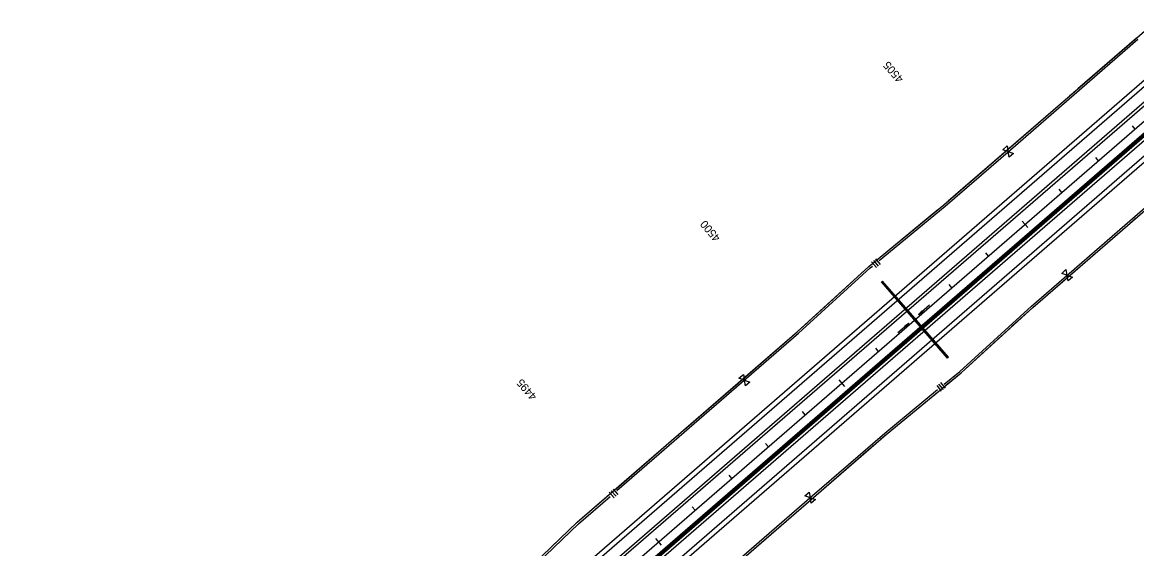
# Model space of a CAD drawing. Extents: x 192699 to 285914, y 194342 to 233219.
# Drawn here: x 198915 to 201213, y 200182 to 201267 of the extents above; entities that cross this region are included whole.
import ezdxf

# ---------------------------------------------------------------- set-up
doc = ezdxf.new("R2010")
doc.units = 0
for name, color, linetype in [('CENT LINE', 7, 'Continuous'), ('CONCRETE', 7, 'Continuous'), ('DRAINAGE', 7, 'Continuous'), ('DRAINAGE ARROWS', 7, 'Continuous'), ('R-W - CofA', 7, 'Continuous'), ('R_Water Annot', 7, 'Continuous'), ('ROAD', 7, 'Continuous'), ('SHOULDER', 7, 'Continuous'), ('STATIONING1', 7, 'Continuous'), ('WRSF', 7, 'Continuous')]:
    doc.layers.add(name, color=color, linetype=linetype)

msp = doc.modelspace()

# ---------------------------------------------------------------- linework, layer by layer
at = {"layer": 'CENT LINE'}
msp.add_line((198833.2, 198989.9), (207514.6, 206505.5), dxfattribs=at)
at = {"layer": 'CONCRETE'}
for p, q in [((198845, 198976.3), (202641.5, 202263)), ((198847.6, 198973.2), (202644.1, 202259.9))]:
    msp.add_line(p, q, dxfattribs=at)
at = {"layer": 'DRAINAGE'}
for p, q in [((200753.5, 200655.2), (200686.8, 200732.2)), ((200755.7, 200657.2), (200689.1, 200734.1)), ((200823, 200574.9), (200756.4, 200651.9)), ((200825.2, 200576.9), (200758.6, 200653.8))]:
    msp.add_line(p, q, dxfattribs=at)
for points in [[(200686.8, 200732.2), (200689.1, 200734.1)], [(200823, 200574.9), (200825.2, 200576.9)]]:
    msp.add_lwpolyline(points, dxfattribs=at)
msp.add_lwpolyline([(200755.8, 200651.4), (200759.1, 200654.3), (200756.3, 200657.6), (200752.9, 200654.7)], close=True, dxfattribs=at)
at = {"layer": 'DRAINAGE ARROWS'}
for p, q in [((200770.1, 200672.3), (200763.6, 200664.6)), ((200772.1, 200670.1), (200763.6, 200664.6)), ((200770.3, 200672.1), (200764.8, 200665.7)), ((200771.9, 200670.2), (200764.8, 200665.7)), ((200770.5, 200671.9), (200766.1, 200666.9)), ((200771.8, 200670.4), (200766.1, 200666.9)), ((200770.6, 200671.8), (200767.4, 200667.9)), ((200771.6, 200670.6), (200767.4, 200667.9)), ((200770.8, 200671.6), (200768.7, 200669.1)), ((200771.4, 200670.8), (200768.7, 200669.1)), ((200771, 200671.4), (200769.9, 200670.2)), ((200771.3, 200671), (200769.9, 200670.2)), ((200772.1, 200670.1), (200770.1, 200672.3)), ((200735.1, 200642), (200743.7, 200647.4)), ((200737.1, 200639.7), (200735.1, 200642)), ((200735.3, 200641.8), (200742.4, 200646.3)), ((200735.4, 200641.6), (200741.1, 200645.2)), ((200735.6, 200641.4), (200739.8, 200644.1)), ((200735.8, 200641.2), (200738.5, 200643)), ((200735.9, 200641.1), (200737.3, 200641.9)), ((200736.2, 200640.7), (200737.3, 200641.9)), ((200736.4, 200640.5), (200738.5, 200643)), ((200736.6, 200640.3), (200739.8, 200644.1)), ((200736.7, 200640.1), (200741.1, 200645.2)), ((200736.9, 200639.9), (200742.4, 200646.3)), ((200737.1, 200639.7), (200743.7, 200647.4))]:
    msp.add_line(p, q, dxfattribs=at)
at = {"layer": 'R-W - CofA'}
for p, q in [((200937, 201004.7), (200946, 201012.5)), ((200948.3, 201000.7), (200937, 201004.7)), ((200946, 201012.5), (200948.3, 201000.7)), ((200950.5, 200989), (200948.3, 201000.7)), ((200948.3, 201000.7), (200959.5, 200996.8)), ((200959.5, 200996.8), (200950.5, 200989)), ((200666.7, 200773.3), (200676.4, 200761.6)), ((200670.6, 200776.5), (200680.3, 200764.8)), ((200674.5, 200779.8), (200684.2, 200768)), ((201058.7, 200749.9), (201067.4, 200757.5)), ((201069.6, 200746), (201058.7, 200749.9)), ((201067.4, 200757.5), (201069.6, 200746)), ((201071.8, 200734.6), (201069.6, 200746)), ((201069.6, 200746), (201080.6, 200742.2)), ((201080.6, 200742.2), (201071.8, 200734.6)), ((200393, 200533.7), (200402.1, 200541.6)), ((200402.1, 200541.6), (200404.3, 200529.8)), ((200404.3, 200529.8), (200393, 200533.7)), ((200406.6, 200518.1), (200404.3, 200529.8)), ((200404.3, 200529.8), (200415.6, 200525.9)), ((200415.6, 200525.9), (200406.6, 200518.1)), ((200801, 200518.5), (200810.4, 200507)), ((200804.8, 200521.6), (200814.2, 200510.2)), ((200808.6, 200524.7), (200818, 200513.3)), ((200133.4, 200305.3), (200143.3, 200293.9)), ((200125.7, 200298.7), (200135.7, 200287.2)), ((200129.6, 200302), (200139.5, 200290.5)), ((200528.9, 200291.2), (200537.6, 200298.8)), ((200539.8, 200287.4), (200528.9, 200291.2)), ((200537.6, 200298.8), (200539.8, 200287.4)), ((200542, 200276), (200539.8, 200287.4)), ((200539.8, 200287.4), (200550.8, 200283.6)), ((200550.8, 200283.6), (200542, 200276))]:
    msp.add_line(p, q, dxfattribs=at)
for points in [[(198915, 198895.4), (200006.2, 199840), (200088.4, 199897.9), (200242.8, 200025.1), (200696.5, 200417.8), (200851, 200544.9), (200998.9, 200679.6), (203115.8, 202512.2), (203289.9, 202616.7), (203516.7, 202813), (203710.8, 203047.2)], [(198751.4, 199084.4), (199842.6, 200029.1), (200059.6, 200236.8), (200513.2, 200629.5), (200661.1, 200764.1), (200815.6, 200891.3), (201571.7, 201545.8), (201608, 201656.6), (201834.8, 201853), (202018.7, 201946.1), (202926, 202731.5), (203067.4, 202873.7)], [(200952.8, 201004.7), (201215.7, 201232.2)], [(201092.1, 201130.6), (201213, 201235.3)], [(200950.1, 201007.7), (201071.1, 201112.4)], [(201075, 201115.8), (201079.6, 201119.8)], [(201083.5, 201123.2), (201088.2, 201127.2)], [(200682.5, 200776.5), (200818.2, 200888.2), (200952.8, 201004.7)], [(200824.7, 200899.1), (200950.1, 201007.7)], [(201074, 200749.9), (201330.1, 200971.5)], [(200679.9, 200779.6), (200803.4, 200881.2)], [(200807.4, 200884.5), (200812.2, 200888.4)], [(200816.1, 200891.7), (200820.8, 200895.7)], [(201206.5, 200859.3), (201211.1, 200863.3)], [(201076.6, 200746.9), (201194.4, 200848.8)], [(201198.2, 200852.1), (201202.7, 200856.1)], [(200547.3, 200660.5), (200661.1, 200764.1), (200665.8, 200768)], [(200408.8, 200533.7), (200515.9, 200626.4), (200663.8, 200761.1), (200668.4, 200764.9)], [(200816.3, 200521.5), (200848.4, 200547.9), (200996.3, 200682.5), (201074, 200749.9)], [(200955.4, 200640), (200998.9, 200679.6), (201076.6, 200746.9)], [(200539, 200652.9), (200543.5, 200657.1)], [(200406.2, 200536.8), (200513.2, 200629.5), (200526.8, 200641.8)], [(200530.6, 200645.3), (200535.2, 200649.5)], [(200939.1, 200625.2), (200943.5, 200629.2)], [(200947.3, 200632.6), (200951.7, 200636.6)], [(200818.8, 200518.5), (200851, 200544.9), (200935.4, 200621.8)], [(200280.7, 200428.2), (200406.2, 200536.8)], [(200141.4, 200302.3), (200408.8, 200533.7)], [(200544.2, 200291.2), (200693.9, 200420.8), (200802.6, 200510.2)], [(200685.1, 200407.9), (200696.5, 200417.8), (200805.1, 200507.2)], [(200272.2, 200420.8), (200276.8, 200424.8)], [(200138.8, 200305.3), (200259.7, 200410)], [(200263.6, 200413.4), (200268.3, 200417.4)], [(200668.4, 200393.5), (200672.9, 200397.4)], [(200676.7, 200400.7), (200681.3, 200404.6)], [(200546.8, 200288.2), (200664.6, 200390.2)], [(199873.7, 200053.2), (200062.3, 200233.8), (200127.6, 200290.3)], [(200006.5, 200186), (200059.6, 200236.8), (200125, 200293.4)], [(200283.8, 200065.7), (200544.2, 200291.2)], [(200424.6, 200182.4), (200546.8, 200288.2)]]:
    msp.add_lwpolyline(points, dxfattribs=at)
at = {"layer": 'R_Water Annot'}
for p, q in [((200786.2, 200684.3), (200763.6, 200664.6)), ((200770.1, 200672.3), (200763.6, 200664.6)), ((200772.1, 200670.1), (200763.6, 200664.6)), ((200770.3, 200672.1), (200764.8, 200665.7)), ((200771.9, 200670.2), (200764.8, 200665.7)), ((200770.5, 200671.9), (200766.1, 200666.9)), ((200771.8, 200670.4), (200766.1, 200666.9)), ((200770.6, 200671.8), (200767.4, 200667.9)), ((200771.6, 200670.6), (200767.4, 200667.9)), ((200770.8, 200671.6), (200768.7, 200669.1)), ((200771.4, 200670.8), (200768.7, 200669.1)), ((200771, 200671.4), (200769.9, 200670.2)), ((200771.3, 200671), (200769.9, 200670.2)), ((200772.1, 200670.1), (200770.1, 200672.3)), ((200720.9, 200627.8), (200743.7, 200647.4)), ((200735.1, 200642), (200743.7, 200647.4)), ((200737.1, 200639.7), (200735.1, 200642)), ((200735.3, 200641.8), (200742.4, 200646.3)), ((200735.4, 200641.6), (200741.1, 200645.2)), ((200735.6, 200641.4), (200739.8, 200644.1)), ((200735.8, 200641.2), (200738.5, 200643)), ((200735.9, 200641.1), (200737.3, 200641.9)), ((200736.2, 200640.7), (200737.3, 200641.9)), ((200736.4, 200640.5), (200738.5, 200643)), ((200736.6, 200640.3), (200739.8, 200644.1)), ((200736.7, 200640.1), (200741.1, 200645.2)), ((200736.9, 200639.9), (200742.4, 200646.3)), ((200737.1, 200639.7), (200743.7, 200647.4))]:
    msp.add_line(p, q, dxfattribs=at)
at = {"layer": 'ROAD'}
for p, q in [((198797.8, 199030.7), (207479.2, 206546.3)), ((198813.5, 199012.5), (207494.9, 206528.2)), ((198852.8, 198967.2), (207534.2, 206482.8)), ((198868.5, 198949), (207549.9, 206464.7))]:
    msp.add_line(p, q, dxfattribs=at)
at = {"layer": 'SHOULDER'}
for p, q in [((198791.3, 199038.2), (202634.7, 202365.5)), ((198817.5, 199008), (202614, 202294.7)), ((198848.9, 198971.7), (202645.4, 202258.4)), ((198875.1, 198941.5), (202704.2, 202256.4))]:
    msp.add_line(p, q, dxfattribs=at)
at = {"layer": 'STATIONING1'}
for points in [[(201203.8, 201054), (201209.7, 201047.2)], [(201128.2, 200988.6), (201134.1, 200981.8)], [(201052.6, 200923.1), (201058.5, 200916.3)], [(200977, 200857.7), (200988.7, 200844.1)], [(200901.4, 200792.2), (200907.3, 200785.4)], [(200825.8, 200726.8), (200831.6, 200720)], [(200750.2, 200661.3), (200756, 200654.5)], [(200674.5, 200595.9), (200680.4, 200589.1)], [(200598.9, 200530.4), (200610.7, 200516.8)], [(200523.3, 200465), (200529.2, 200458.2)], [(200447.7, 200399.5), (200453.6, 200392.7)], [(200372.1, 200334.1), (200378, 200327.3)], [(200296.5, 200268.6), (200302.4, 200261.8)], [(200220.9, 200203.2), (200232.7, 200189.6)]]:
    msp.add_lwpolyline(points, dxfattribs=at)
at = {"layer": 'WRSF'}
msp.add_line((198846.3, 198974.7), (202676.8, 202290.9), dxfattribs=at)

# ---------------------------------------------------------------- texts
at = {"layer": 'STATIONING1'}
for s, p in [('4505', (200733.6, 201151.4)), ('4500', (200356, 200823.7)), ('4495', (199977.5, 200496.9))]:
    msp.add_text(s, height=16.5, rotation=130.8833, dxfattribs=at).set_placement(p)

doc.saveas('drawing.dxf')
